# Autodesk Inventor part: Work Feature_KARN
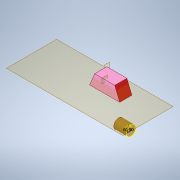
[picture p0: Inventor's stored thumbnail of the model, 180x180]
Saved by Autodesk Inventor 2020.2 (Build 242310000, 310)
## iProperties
Created: 2018-06
Part Number: Work Feature_KARN
Material: Generic
Document SubType Name: Modeling
Designer: Power User
Density: 1 g/cm^3
Appearance: Light Red
Author: Power User
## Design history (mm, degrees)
sketch "Sketch1"
  geometry: L1 (0, 0)-(50, 0); L2 (50, 0)-(50, -50); L3 (50, -50)-(0, -50); L4 (0, -50)-(0, 0); 1 further point
  constraints: 8 end point, 2 parallel, 1 coincident, 1 horizontal, 1 perpendicular
  dimensions: "d0" = 50 distance of L1.end L2.end; "d1" = 50 distance of L2.end L3.end; "d53" = 0 distance from line of point (0, 0) L4
extrude "Extrusion1" new body sketch "Sketch1" distance "d2" = 50; taper "d3" = 0 deg
workplane "Work Plane1"
sketch "Sketch2"
  geometry: L1 (0, 50)-(50, 50) reference; L2 (50, 0)-(50, 50) reference; C1 r 20 at (-30, 25); 3 further points
  constraints: 2 midpoint, 1 centre point, 1 horizontal alignment
  dimensions: "d5" = 40 diameter of C1; "d54" = 30 horizontal distance of C1.centre point (0, 0)
extrude "Extrusion2" new body sketch "Sketch2" distance "d6" = 50; taper "d7" = 0 deg
sketch "Sketch3"
  geometry: L1 (-172.16, 49.98)-(-172.16, 11.482); C1 r 7.5 at (-197.16, 26.587); 1 further point
  constraints: 2 end point, 1 centre point, 1 vertical
  dimensions: "d8" = 15 diameter of C1; "d9" = 50 diameter of C1.centre L1
revolve "Revolution1" sketch "Sketch3" stored, may be unused: angle "d10" = 90 deg
workplane "Work Plane2"
sketch "Sketch4"
  geometry: L1 (-98.807, 58.325)-(-98.807, 8.325); A1 r 25 centre (-98.807, 33.325) between (-98.807, 58.325) and (-98.807, 8.325); 1 further point
  constraints: 2 end point, 2 point on circle, 1 centre point, 1 vertical
  dimensions: "d12" = 50 diameter of A1
revolve "Revolution2" sketch "Sketch4" stored, may be unused: angle "d13" = 90 deg
workplane "Work Plane3"
sketch "Sketch5"
  geometry: L1 (-192.037, 9.98)-(-171.326, 59.98); L2 (-171.326, 59.98)-(-89.041, 59.98); L3 (-89.041, 59.98)-(-68.33, 9.98); L4 (-68.33, 9.98)-(-192.037, 9.98); L5 (-130.184, 59.98)-(-130.184, 9.98); 1 further point
  constraints: 10 end point, 2 midpoint, 1 horizontal, 1 parallel, 1 perpendicular, 1 other
  dimensions: "d15" = 50 distance between parallel lines of L4 L2; "d16" = 45 deg angle of L3 L1
extrude "Extrusion3" new body sketch "Sketch5" stored distance "d17" = 50; taper "d18" = 0 deg
sketch "Sketch6"
  geometry: L1 (15, 35)-(35, 35); L2 (35, 35)-(35, 15); L3 (35, 15)-(15, 15); L4 (15, 15)-(15, 35); L5 (0, 50)-(50, 50) reference; L6 (0, 0)-(0, 50) reference; 5 further points
  constraints: 4 midpoint, 1 horizontal alignment, 1 vertical alignment, 2 other
  dimensions: "d19" = 20 distance of L1.start L1.end; "d20" = 20 distance of L1.end L2.end
emboss "Emboss1" sketch "Sketch6" dims "d21" = 0.2, "d22" = 0
sketch "Sketch7"
  geometry: L1 (-35, 35)-(-15, 35); L2 (-15, 35)-(-15, 15); L3 (-15, 15)-(-35, 15); L4 (-35, 15)-(-35, 35); L5 (0, 50)-(-50, 50) reference; L6 (-50, 50)-(-50, 0) reference; 5 further points
  constraints: 4 midpoint, 1 horizontal alignment, 1 vertical alignment, 2 other
  dimensions: "d23" = 20 distance of L1.start L1.end; "d24" = 20 distance of L3.end L1.start
emboss "Emboss2" sketch "Sketch7" dims "d25" = 0.2, "d26" = 0
sketch "Sketch8"
  geometry: L1 (15, 35)-(35, 35); L2 (35, 35)-(35, 15); L3 (35, 15)-(15, 15); L4 (15, 15)-(15, 35); L5 (0, 0)-(0, 50) reference; L6 (0, 50)-(50, 50) reference; 4 further points
  constraints: 4 midpoint, 1 horizontal alignment, 1 vertical alignment, 2 other
  dimensions: "d27" = 20 distance of L1.start L1.end; "d28" = 20 distance of L3.end L1.start
emboss "Emboss3" sketch "Sketch8" dims "d29" = 0.2, "d30" = 0
sketch "Sketch9"
  geometry: L1 (-11.219, -35.018)-(-35.694, -35.018); L2 (-35.694, -35.018)-(-35.694, -14.982); L3 (-35.694, -14.982)-(-11.219, -14.982); L4 (-11.219, -14.982)-(-11.219, -35.018); L5 (0, -50)-(0, 0) reference; 4 further points
  constraints: 3 midpoint, 1 horizontal alignment, 1 vertical alignment, 2 other
emboss "Emboss4" sketch "Sketch9" dims "d31" = 0.2, "d32" = 0
sketch "Sketch10"
  geometry: L1 (15, 35)-(35, 35); L2 (35, 35)-(35, 15); L3 (35, 15)-(15, 15); L4 (15, 15)-(15, 35); L5 (0, 50)-(50, 50) reference; L6 (0, 0)-(0, 50) reference; 5 further points
  constraints: 4 midpoint, 1 horizontal alignment, 1 vertical alignment, 2 other
  dimensions: "d33" = 20 distance of L1.start L1.end; "d34" = 20 distance of L3.end L1.start
emboss "Emboss5" sketch "Sketch10" dims "d35" = 0.2, "d36" = 0
sketch "Sketch11"
  geometry: L1 (15, 35)-(35, 35); L2 (35, 35)-(35, 15); L3 (35, 15)-(15, 15); L4 (15, 15)-(15, 35); L5 (0, 0)-(0, 50) reference; L6 (0, 50)-(50, 50) reference; 4 further points
  constraints: 4 midpoint, 1 horizontal alignment, 1 vertical alignment, 2 other
  dimensions: "d37" = 20 distance of L1.start L1.end; "d38" = 20 distance of L1.end L2.end
emboss "Emboss6" sketch "Sketch11" dims "d39" = 0.2, "d40" = 0
sketch "Sketch12"
  geometry: L1 (118.439, 97.246)-(43.439, 97.246); L2 (43.439, 97.246)-(43.439, 172.246); L3 (43.439, 172.246)-(58.439, 172.246); L4 (58.439, 172.246)-(58.439, 112.246); L5 (58.439, 112.246)-(118.439, 112.246); L6 (118.439, 112.246)-(118.439, 97.246); 1 further point
  constraints: 12 end point, 4 perpendicular, 1 horizontal, 1 vertical
  dimensions: "d41" = 75 distance of L1.start L1.end; "d42" = 75 distance of L1.end L2.end (= d41); "d43" = 15 distance of L5.end L1.start; "d44" = 15 distance of L2.end L3.end (= d43)
extrude "Extrusion4" new body sketch "Sketch12" stored distance "d45" = 100; taper "d46" = 0 deg
sketch "Sketch13"
  geometry: L1 (97.246, 118.439)-(97.246, 43.439) reference; L2 (97.246, 43.439)-(172.246, 43.439) reference; L3 (172.246, 43.439)-(97.246, 43.439) reference; L4 (172.246, 118.439)-(97.246, 118.439); L5 (97.246, 118.439)-(97.246, 43.439); L6 (97.246, 43.439)-(172.246, 43.439); L7 (172.246, 43.439)-(172.246, 118.439); L8 (172.246, 118.439)-(97.246, 43.439); L9 (97.246, 118.439)-(172.246, 43.439); 2 further points
  constraints: 12 end point, 2 equal length, 2 midpoint, 2 parallel, 1 horizontal, 1 perpendicular
extrude "Extrusion5" join sketch "Sketch13" distance "d47" = 15; taper "d48" = 0 deg
feature "Move Body1"
workplane "Work Plane4"
workplane "Work Plane5"
workplane "Work Plane6"
workplane "Work Plane7"
workplane "Work Plane8"
workplane "Work Plane9"
workplane "Work Plane10"
workplane "Work Plane11"
sketch "Sketch14"
  geometry: L1 (34.092, -0.245)-(29.02, -0.245) reference; L2 (29.02, -0.245)-(28.734, 0) reference; L3 (28.734, 0)-(0, 0) reference; L4 (0, 0)-(15.863, 27.475) reference; L5 (15.671, 27.633)-(17.1, 30.109) reference; L6 (17.254, 29.885)-(19.895, 34.46) reference; L7 (19.612, 34.459)-(20.93, 36.742) reference; L8 (20.93, 36.742)-(21.213, 36.742) reference; L9 (21.213, 36.742)-(35.355, 61.237) reference; L10 (35.355, 61.237)-(52.54, 31.472) reference; L11 (52.54, 31.472)-(52.682, 31.717) reference; L12 (52.682, 31.717)-(55.407, 26.996) reference; L13 (55.407, 26.996)-(55.125, 26.996) reference; L14 (55.125, 26.996)-(70.711, 0) reference; L15 (70.711, 0)-(38.546, 0) reference; L16 (38.546, 0)-(38.616, -0.245) reference; L17 (38.616, -0.245)-(36.073, -0.245) reference; L18 (36.073, -0.245)-(35.999, 0) reference; L19 (35.999, 0)-(33.823, 0) reference; L20 (33.823, 0)-(34.092, -0.245) reference; 1 further point
  constraints: 3 other
extrude "Extrusion6" cut sketch "Sketch14" extent not by distance; stored distance "d58" = 211.595; taper "d59" = 0 deg
workplane "Work Plane12"
workplane "Work Plane13"
workplane "Work Plane14"
sketch "Sketch15"
  geometry: L1 (0, 0)-(-20, 0); L2 (0, 0)-(-10, 17.321); 3 further points
  constraints: 4 end point, 1 coincident, 1 horizontal, 1 horizontal alignment, 3 other
  dimensions: "d60" = 60 deg angle of L2 L1
workplane "Work Plane15"
workplane "Work Plane16"
workplane "Work Plane17"
workplane "Work Plane18"
node "Cube"
node "Cylinder"
node "Ring"
node "Sphere"
node "Trapezoid"
node "Solid"
node "Project Cut Edges1"
other parameters: "d14" = -87.5, "d57" = -30 deg
